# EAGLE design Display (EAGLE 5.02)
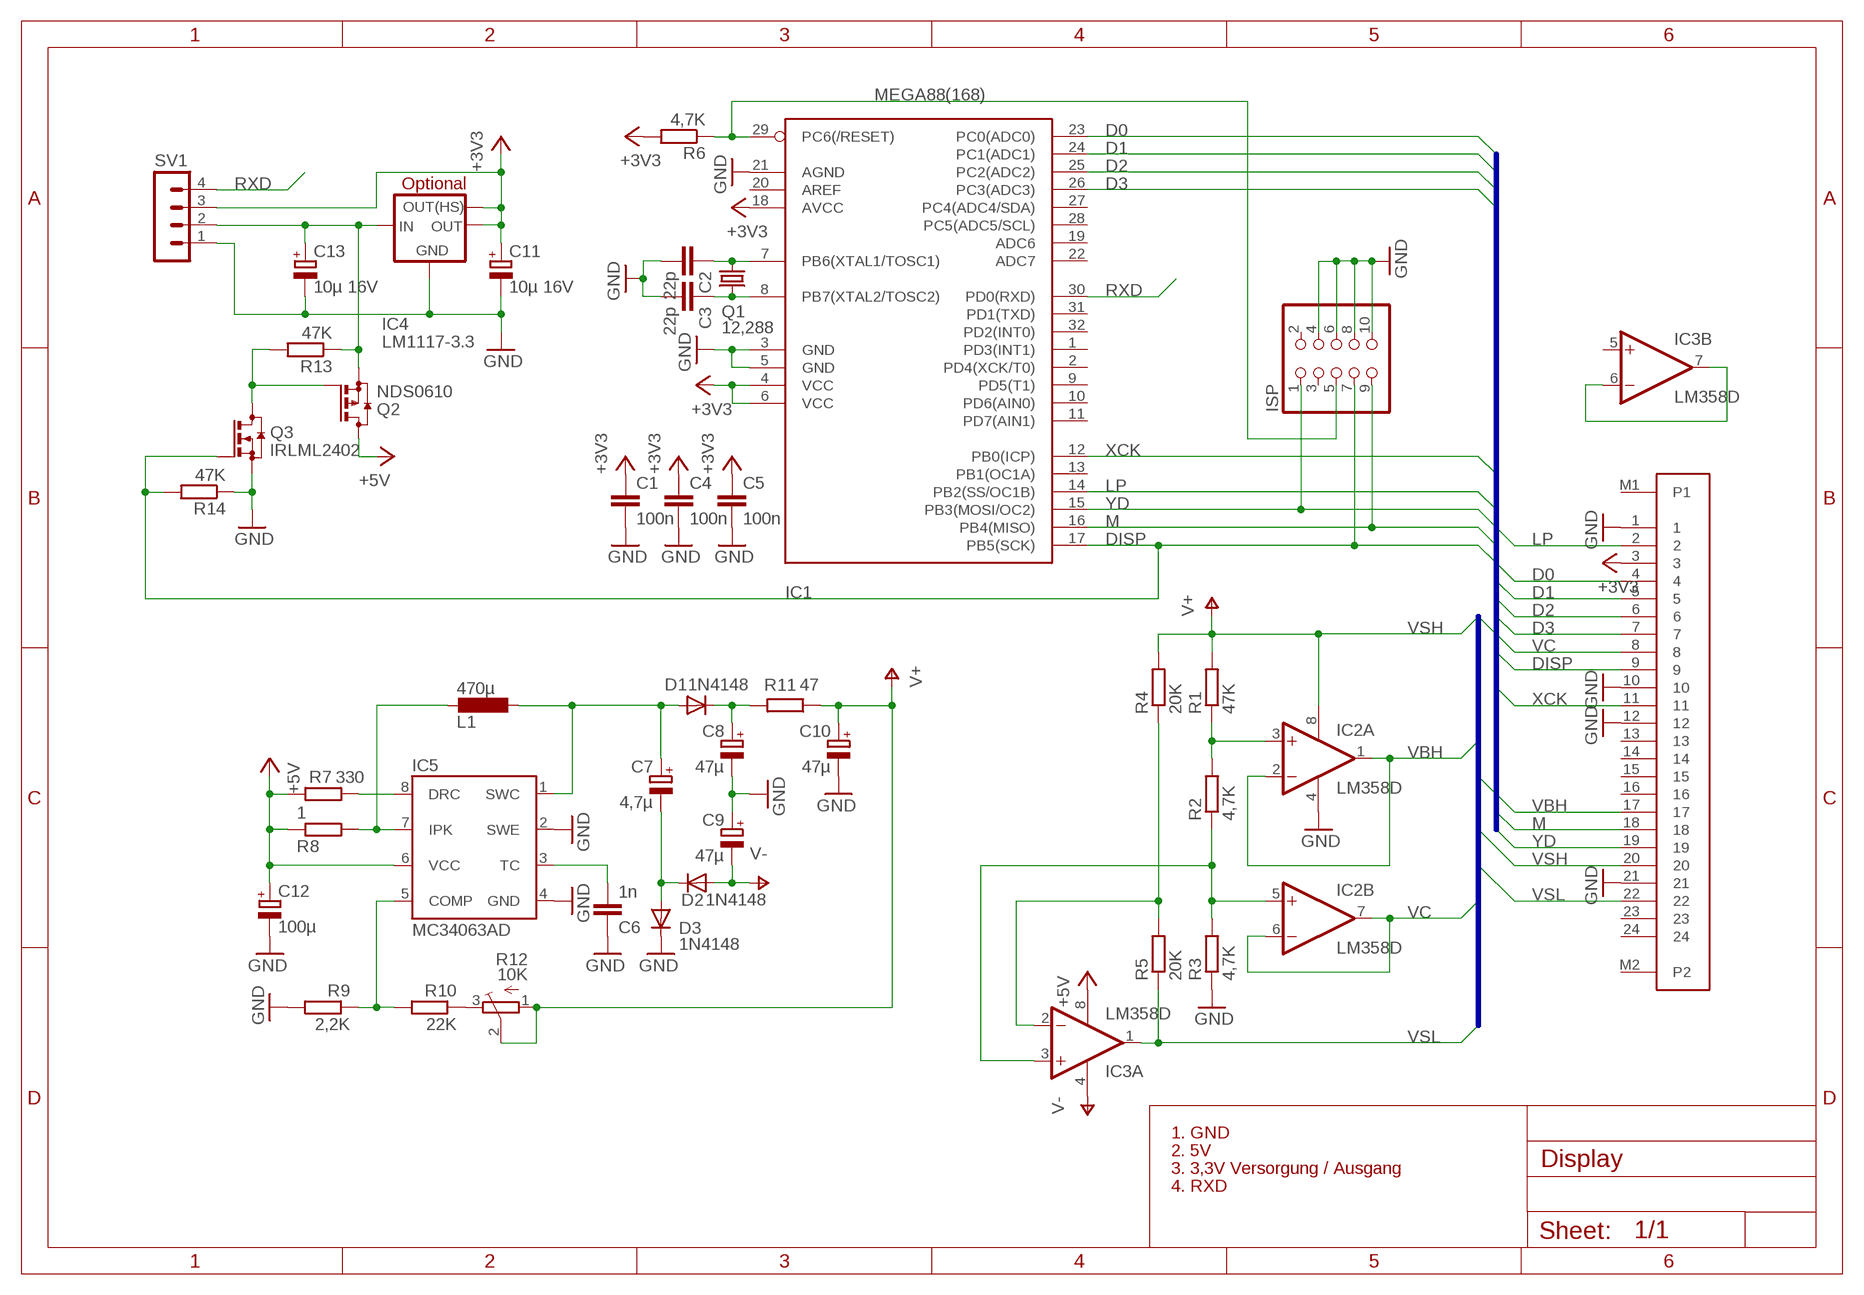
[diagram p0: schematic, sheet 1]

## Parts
C1  100n  C-EUC0402  [C0402]
C2  22p  C-EUC0603  [C0603]
C3  22p  C-EUC0603  [C0603]
C4  100n  C-EUC0402  [C0402]
C5  100n  C-EUC0402  [C0402]
C6  1n  C-EUC0603  [C0603]
C7  4,7µ  CPOL-EU153CLV-0405  [153CLV-0405]
C8  47µ  CPOL-EU153CLV-0605  [153CLV-0605]
C9  47µ  CPOL-EU153CLV-0605  [153CLV-0605]
C10  47µ  CPOL-EU153CLV-0605  [153CLV-0605]
C11  10µ 16V  CPOL-EU153CLV-0405  [153CLV-0405]
C12  100µ  CPOL-EU153CLV-0605  [153CLV-0605]
C13  10µ 16V  CPOL-EU153CLV-0405  [153CLV-0405]
D1  1N4148  DIODE-SOD80C  [SOD80C]
D2  1N4148  DIODE-SOD80C  [SOD80C]
D3  1N4148  DIODE-SOD80C  [SOD80C]
IC1  MEGA88(168)  MEGA8-AI  [TQFP32-08]
IC2  LM358D  [SO08]
IC3  LM358D  [SO08]
IC4  LM1117-3.3  LM1117-HS  [SOT223]
IC5  MC34063AD  [SO08]
ISP  PINHD-2X5_2.54-SMD  [2X05SMD]
L1  470µ  DO3316P  [DO3316P]
Q1  12,288  CRYSTALHC49UP  [HC49UP]
Q2  NDS0610  [SOT23]
Q3  IRLML2402  [SOT23]
R1  47K  R-EU_R0805-MOD  [R0805-MOD]
R2  4,7K  R-EU_R0805-MOD  [R0805-MOD]
R3  4,7K  R-EU_R0805-MOD  [R0805-MOD]
R4  20K  R-EU_R0805-MOD  [R0805-MOD]
R5  20K  R-EU_R0805-MOD  [R0805-MOD]
R6  4,7K  R-EU_R0805-MOD  [R0805-MOD]
R7  330  R-EU_R0805-MOD  [R0805-MOD]
R8  1  R-EU_R0805-MOD  [R0805-MOD]
R9  2,2K  R-EU_R0805-MOD  [R0805-MOD]
R10  22K  R-EU_R0805-MOD  [R0805-MOD]
R11  47  R-EU_R0805-MOD  [R0805-MOD]
R12  10K  TRIM_EU-SM-42/43B  [SM-42/43B]
R13  47K  R-EU_R0805-MOD  [R0805-MOD]
R14  47K  R-EU_R0805-MOD  [R0805-MOD]
SV1  MA04-1  [MA04-1]
X1  FL24-0.5  [FL24-0.5]

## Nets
+3V3: C1.1 C4.1 C5.1 C11.+ IC1.4(VCC) IC1.6(VCC) IC1.18(AVCC) IC4.2(OUT) IC4.4(OUT2) R6.2 SV1.3 X1.3
+5V: C12.+ IC3.8(P:V+) IC5.6(VCC) Q2.3(D) R7.1 R8.1
D0: IC1.23(PC0(ADC0)) X1.4
D1: IC1.24(PC1(ADC1)) X1.5
D2: IC1.25(PC2(ADC2)) X1.6
D3: IC1.26(PC3(ADC3)) X1.7
DISP: IC1.17(PB5(SCK)) ISP.7 Q3.1(G) R14.2 X1.9
GND: C1.2 C2.2 C3.2 C4.2 C5.2 C6.1 C8.- C9.+ C10.- C11.- C12.- C13.- D3.C IC1.3(GND) IC1.5(GND) IC1.21(AGND) IC2.4(P:V-) IC4.1(GND) IC5.2(SWE) IC5.4(GND) ISP.4 ISP.6 ISP.8 ISP.10 Q3.2(S) R3.1 R9.2 R14.1 SV1.1 X1.1 X1.10 X1.12 X1.21
LP: IC1.14(PB2(SS/OC1B)) X1.2
M: IC1.16(PB4(MISO)) ISP.9 X1.18
N$1: C3.1 IC1.8(PB7(XTAL2/TOSC2)) Q1.2
N$2: IC3.6(B:-IN) IC3.7(B:OUT)
N$3: C2.1 IC1.7(PB6(XTAL1/TOSC1)) Q1.1
N$4: IC2.3(A:+IN) R1.1 R2.2
N$5: IC2.5(B:+IN) IC3.3(A:+IN) R2.1 R3.2
N$6: IC1.29(PC6(/RESET)) ISP.5 R6.1
N$7: IC3.2(A:-IN) R4.1 R5.2
N$8: IC5.8(DRC) R7.2
N$9: IC5.7(IPK) L1.1 R8.2
N$10: C7.+ D1.A IC5.1(SWC) L1.2
N$11: C8.+ D1.C R11.2
N$12: IC5.5(COMP) R9.1 R10.2
N$13: C6.2 IC5.3(TC)
N$14: C13.+ IC4.3(IN) Q2.2(S) R13.1 SV1.2
N$15: C7.- D2.C D3.A
N$16: R10.1 R12.3(E)
N$18: Q2.1(G) Q3.3(D) R13.2
RXD: IC1.30(PD0(RXD)) SV1.4
V-: C9.- D2.A IC3.4(P:V-)
VBH: IC2.1(A:OUT) IC2.2(A:-IN) X1.17
VC: IC2.6(B:-IN) IC2.7(B:OUT) X1.8
VSH: C10.+ IC2.8(P:V+) R1.2 R4.2 R11.1 R12.1(A) R12.2(S) X1.20 ; supply symbol labelled V+
VSL: IC3.1(A:OUT) R5.1 X1.22
XCK: IC1.12(PB0(ICP)) X1.11
YD: IC1.15(PB3(MOSI/OC2)) ISP.1 X1.19
Unconnected: IC1.1(PD3(INT1)) IC1.2(PD4(XCK/T0)) IC1.9(PD5(T1)) IC1.10(PD6(AIN0)) IC1.11(PD7(AIN1)) IC1.13(PB1(OC1A)) IC1.19(ADC6) IC1.20(AREF) IC1.22(ADC7) IC1.27(PC4(ADC4/SDA)) IC1.28(PC5(ADC5/SCL)) IC1.31(PD1(TXD)) IC1.32(PD2(INT0)) IC3.5(B:+IN) ISP.2 ISP.3 X1.13 X1.14 X1.15 X1.16 X1.23 X1.24 X1.M1(P1) X1.M2(P2)

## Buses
D[0..3],LP,XCK,M,YD,DISP
VSH,VBH,VC,VSL

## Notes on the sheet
- Optional
- 1. GND
- 2. 5V
- 3. 3,3V Versorgung / Ausgang
- 4. RXD

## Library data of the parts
C1-C6 = rcl:C-EU: CAPACITOR, European symbol
C7-C13 = rcl:CPOL-EU: POLARIZED CAPACITOR, European symbol
D1-D3 = diode:DIODE-: DIODE
IC1 = atmel:MEGA8: MICROCONTROLLER 8 Kbytes FLASH, 1 kbytes SRAM, 512 bytes EEPROM, USART, 6-channel 10 bit ADC, 2-channel 8 bit ADC Pin compatible with Atmega48, ATMega88, ATMega168 Source: avr.lbr
IC2 IC3 = linear:LM358: OP AMP also LM158; LM258; LM2904 Source: http://cache.national.com/ds/LM/LM158.pdf
IC4 = v-reg-3:LM1117-HS
IC5 = v-reg-3:MC34063A: 1.5A Step-Up/Down/Inverting Switching Regulator NPN Darlington Switch, Vin 3V to 40V, Current Limiter Input, adjustable Frequency up to 100kHz
ISP = pinhead-1:PINHD-2X5: PIN HEADER
L1 = inductor-coilcraft:DO3316P: COILCRAFT
Q1 = crystal:CRYSTAL: CRYSTAL
Q2 = SMD MOSFET:NDS0610: P-CHANNEL MOS FET
Q3 = SMD MOSFET:IRLML2402: N-CHANNEL MOS FET
R1-R11 R13 R14 = rcl:R-EU_: RESISTOR, European symbol
R12 = pot:TRIM_EU-: POTENTIOMETER
SV1 = con-lstb:MA04-1: PIN HEADER
X1 = Flexprint:FL24-0.5

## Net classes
0 digital: width 0.203 mm, clearance 0.102 mm

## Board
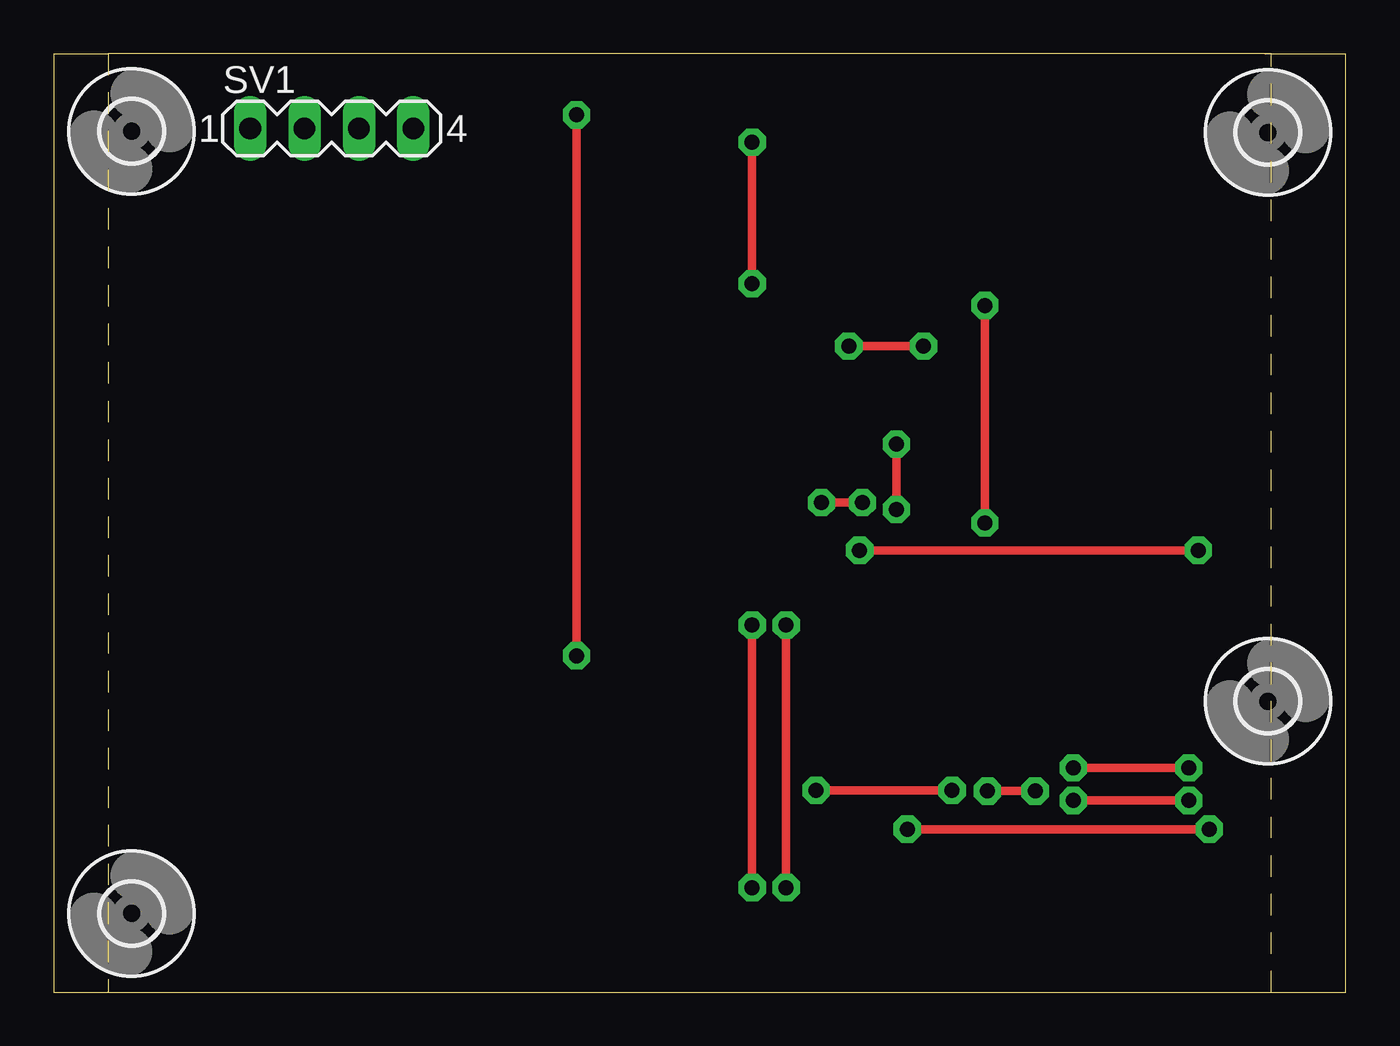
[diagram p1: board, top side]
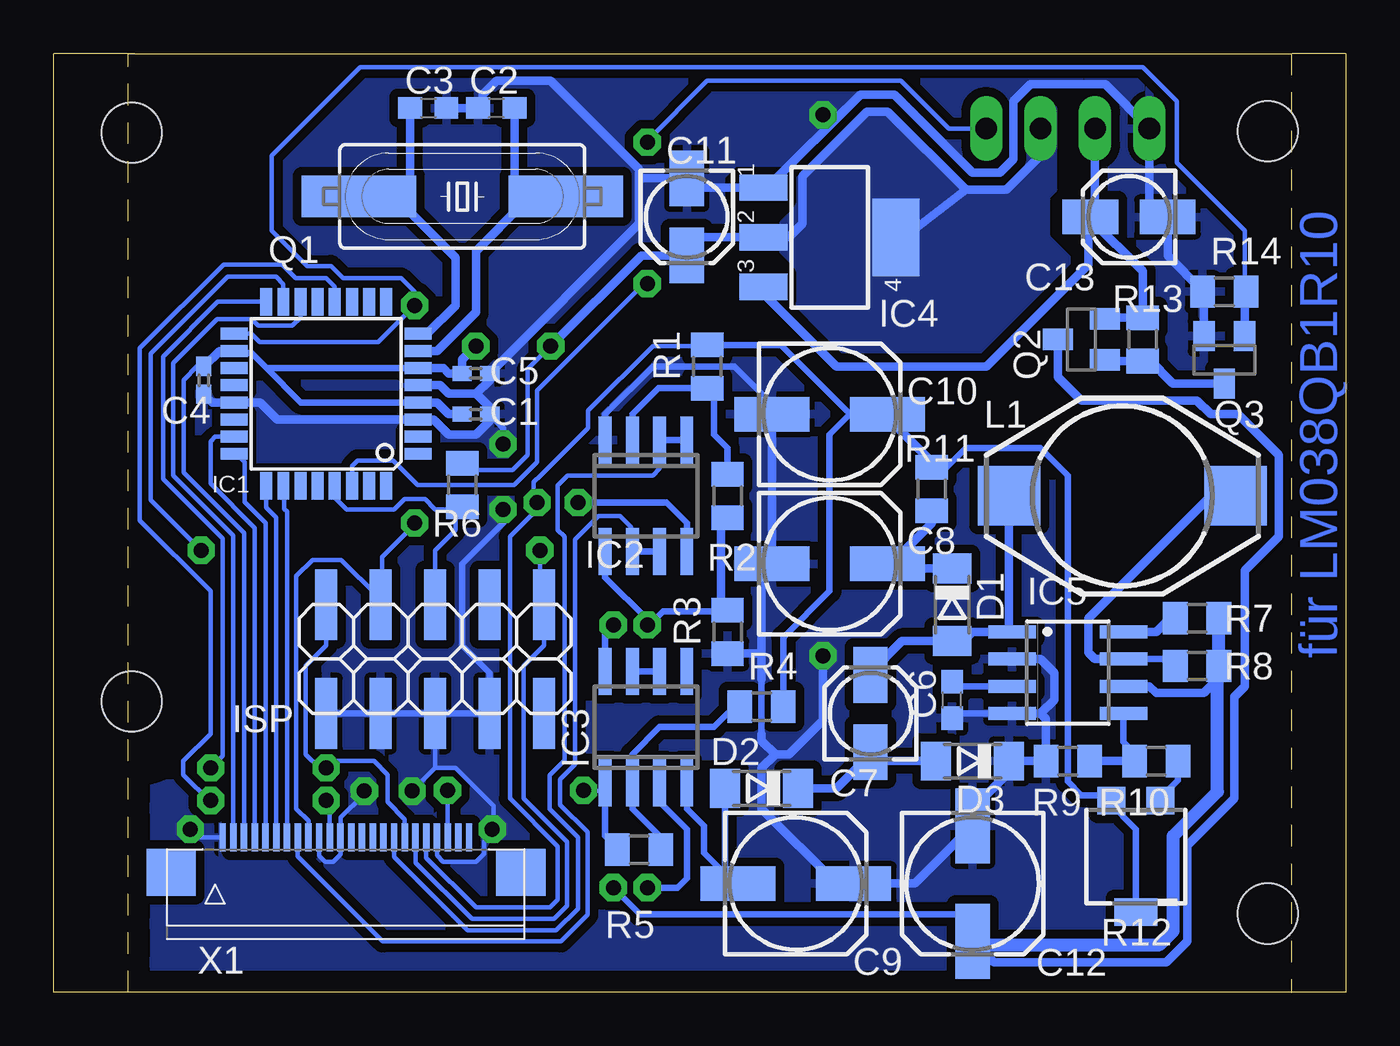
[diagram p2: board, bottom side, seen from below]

Size 60.31 x 43.81 mm. Coordinates in mm from the lower left corner, seen from the top.
Outline: 2.53,0 2.54,0 2.54,43.81 56.82,43.81 56.82,0
Outline: 2.53,0 56.82,0
Outline: 60.31,43.81 60.31,0 56.82,0
Outline: 56.51,0 56.82,0
Outline: 56.51,43.82 60.31,43.82
Outline: 0,43.81 0,0 2.53,0
Outline: 0,43.82 2.53,43.82
Copper layers (1*16): Top 0.035mm / dielectric 1.5mm / Bottom 0.035mm
Design rules "default": minimum track width 10mil, minimum drill 24mil, track to track 8mil, track to pad 8mil, pad to pad 8mil, via to via 8mil, smd to smd 8mil, copper to edge 40mil, drill to drill 8mil, minimum pad ring 10mil, minimum via ring 8mil, stop-mask expansion 4mil, vias tented up to drill 0mil, thermal gap 10mil

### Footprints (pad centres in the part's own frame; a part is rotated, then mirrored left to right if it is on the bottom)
C0402 = smd 0.9 x 0.7: 1 -0.65,0; 2 0.65,0
C0603 = smd 1.1 x 1: 1 -0.85,0; 2 0.85,0
153CLV-0405 = smd 2.6 x 1.6: + 1.8,0; - -1.8,0
153CLV-0605 = smd 3.5 x 1.6: + 2.7,0; - -2.7,0
SOD80C = smd 1.4 x 1.8: A 1.7,0; C -1.7,0
TQFP32-08 = smd 1.27 x 0.559: 1 -4.293,2.8; 2 -4.293,2; 3 -4.293,1.2; 4 -4.293,0.4; 5 -4.293,-0.4; 6 -4.293,-1.2; 7 -4.293,-2; 8 -4.293,-2.8; 17 4.293,-2.8; 18 4.293,-2; 19 4.293,-1.2; 20 4.293,-0.4; 21 4.293,0.4; 22 4.293,1.2; 23 4.293,2; 24 4.293,2.8 | smd 0.559 x 1.27: 9 -2.8,-4.293; 10 -2,-4.293; 11 -1.2,-4.293; 12 -0.4,-4.293; 13 0.4,-4.293; 14 1.2,-4.293; 15 2,-4.293; 16 2.8,-4.293; 25 2.8,4.293; 26 2,4.293; 27 1.2,4.293; 28 0.4,4.293; 29 -0.4,4.293; 30 -1.2,4.293; 31 -2,4.293; 32 -2.8,4.293
SO08 = smd 0.6 x 2.2: 1 -1.905,-2.6; 2 -0.635,-2.6; 3 0.635,-2.6; 4 1.905,-2.6; 5 1.905,2.6; 6 0.635,2.6; 7 -0.635,2.6; 8 -1.905,2.6
SOT223 = smd 1.219 x 2.235: 1 -2.311,-3.099; 2 0,-3.099; 3 2.311,-3.099 | smd 3.6 x 2.2: 4 0,3.099
2X05SMD = smd 1.016 x 3.302: 1 -1.27,-3.81; 2 -1.27,1.27; 3 1.27,-3.81; 4 1.27,1.27; 5 3.81,-3.81; 6 3.81,1.27; 7 6.35,-3.81; 8 6.35,1.27; 9 8.89,-3.81; 10 8.89,1.27
DO3316P = smd 2.92 x 2.79: 1 -5.28,0; 2 5.28,0
HC49UP = smd 5.334 x 1.93: 1 -4.826,0; 2 4.826,0
SOT23 = smd 1 x 1.4: 1 -0.95,-1.1; 2 0.95,-1.1; 3 0,1.1
R0805-MOD = smd 1.146 x 1.5: 1 -1.014,0; 2 1.014,0
SM-42/43B = smd 1.3 x 1.3: 1 2.6,1.15; 3 2.6,-1.15 | smd 1.3 x 2: 2 -2.6,0
MA04-1 = drill 1.016 long: 1 -3.81,0; 2 -1.27,0; 3 1.27,0; 4 3.81,0
2,8 = hole 2.8: 0,0
FL24-0.5 = smd 0.3 x 1.3: 1 0,-0.04; 2 0.5,-0.04; 3 1,-0.04; 4 1.5,-0.04; 5 2,-0.04; 6 2.5,-0.04; 7 3,-0.04; 8 3.5,-0.04; 9 4,-0.04; 10 4.5,-0.04; 11 5,-0.04; 12 5.5,-0.04; 13 6,-0.04; 14 6.5,-0.04; 15 7,-0.04; 16 7.5,-0.04; 17 8,-0.04; 18 8.5,-0.04; 19 9,-0.04; 20 9.5,-0.04; 21 10,-0.04; 22 10.5,-0.04; 23 11,-0.04; 24 11.5,-0.04 | smd 2.3 x 2.2: M1 13.911,-1.68; M2 -2.4,-1.68

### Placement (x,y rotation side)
C1  40.6,26.98 0 bottom
C2  39.65,41.27 180 bottom
C3  42.82,41.27 0 bottom
C4  53.3,28.57 270 bottom
C5  40.6,28.89 0 bottom
C6  18.38,13.65 90 bottom
C7  22.19,13.01 90 bottom
C8  24.09,20 0 bottom
C9  25.68,5.07 0 bottom
C10  24.09,26.98 0 bottom
C11  30.76,36.19 270 bottom
C12  17.42,5.07 270 bottom
C13  10.12,36.19 180 bottom
D1  18.38,18.09 270 bottom
D2  27.27,9.52 180 bottom
D3  17.42,10.79 180 bottom
IC1  47.59,27.93 180 bottom
IC2  32.66,23.17 180 bottom
IC3  32.66,12.38 0 bottom
IC4  24.09,35.24 270 bottom
IC5  12.98,14.92 270 bottom
ISP  38.7,14.28 180 bottom
L1  10.44,23.17 180 bottom
Q1  41.24,37.14 180 bottom
Q2  12.34,30.48 90 bottom
Q3  5.68,29.52 180 bottom
R1  29.81,29.21 90 bottom
R2  28.85,23.17 90 bottom
R3  28.85,16.82 90 bottom
R4  27.27,13.33 0 bottom
R5  32.98,6.66 0 bottom
R6  41.24,23.68 90 bottom
R7  6.95,17.46 180 bottom
R8  6.95,15.23 180 bottom
R9  12.98,10.79 180 bottom
R10  8.85,10.79 180 bottom
R11  19.33,23.49 270 bottom
R12  9.8,6.35 90 bottom
R13  9.49,30.48 270 bottom
R14  5.68,32.7 0 bottom
SV1  12.98,40.32 0 top
U$1  [2,8]  56.67,13.58 0 top
U$2  [2,8]  56.67,40.13 0 top
U$3  [2,8]  3.65,40.19 0 top
U$4  [2,8]  3.65,3.68 0 top
X1  52.42,7.27 0 bottom

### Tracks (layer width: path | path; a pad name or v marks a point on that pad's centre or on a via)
+3V3  (via drill 0.7 pad 1.27)
  Top 0.406: v37.11,30.16 v40.6,30.16
  Bottom 0.203: X1.3 51.42,7.38 51.46,7.42 51.42,7.47 51.42,21.45 54.24,24.27 54.24,28.59 53.6,29.22 C4.1 | R6.2 40.98,24.57 40.79,24.38 38.89,24.38 38.19,25.08 38.19,29.08 v37.11,30.16 | v37.11,30.16 37.24,30.03 | v37.11,30.16
  Bottom 0.305: IC1.6 50.37,29.14 | IC1.4 48.77,27.53 50.37,29.14 | 50.37,29.14 51.08,29.84 51.71,29.84 51.81,29.93 IC1.18
  Bottom 0.406: IC1.6 42.12,29.14 41.87,28.89 C5.1 41.24,28.89 41.24,29.52 v40.6,30.16 | IC1.4 42.42,27.53 41.87,26.98 C1.1 | C4.1 53.3,29.21 52.57,29.93 IC1.18 | 17.74,37.46 21.39,41.11 22.35,41.11 25.36,38.1 25.36,35.87 26,35.24 IC4.2 30.12,35.24 30.76,34.6 C11.+ 32.88,34.39 v37.11,30.16 | 17.74,37.46 15.84,37.46 14.25,39.05 SV1.3 | IC4.4 20.6,35.24 17.74,37.46
  pour Bottom (isolate 0.406, no thermals): 13.61,41.27 13.61,37.46 13.93,37.14 13.93,35.24 12.98,34.28 12.98,33.97 17.11,29.84 23.46,29.84 25.68,32.06 25.68,33.97 26.31,34.6 26.31,35.87 25.68,36.51 25.68,38.09 22.31,41.46 21.27,41.46 17.58,37.78 15.52,37.78 14.88,38.41 14.88,41.27
+5V  (via drill 0.7 pad 1.27)
  Top 0.406: v34.19,4.88 v34.19,17.14
  Bottom 0.305: IC3.8 34.57,16.76 v34.19,17.14 | v34.19,4.88 32.95,3.65 18.54,3.65 17.9,3.65 17.42,3.17 C12.+
  Bottom 0.406: IC5.6 9.17,14.28 8.85,13.96 6.63,13.96 5.99,14.6 5.99,14.92 | R7.1 5.99,17.46 5.93,17.4 | Q2.3 13.44,28.72 12.34,27.62 6.95,27.62 6.31,26.98 5.04,26.98 3.14,25.08 3.14,21.27 4.72,19.68 4.72,14.28 5.17,13.84 5.2,13.81 5.2,9.04 7.39,6.85 7.39,2.38 8.38,1.39 16.44,1.39 C12.+
  Bottom 0.61: 5.93,17.4 R8.1 5.93,14.98 5.99,14.92 5.99,9.36 8.06,7.3 8.06,2.85 8.69,2.22 17.42,2.22 C12.+
D0
  Bottom 0.203: IC1.23 52.76,25.93 52.98,25.71 52.98,23.74 50.92,21.68 50.92,7.45 50.89,7.42 50.92,7.39 X1.4
D1
  Bottom 0.203: IC1.24 51.77,25.14 51.4,24.76 51.4,22.89 50.42,21.91 X1.5
D2
  Bottom 0.203: 50.55,23.38 50.39,23.55 IC1.25 50.39,22.64 49.92,22.17 49.92,7.44 49.94,7.42 49.92,7.41 X1.6
D3
  Bottom 0.203: 49.42,23.42 49.59,23.59 IC1.26 49.59,23.33 49.56,23.3 49.56,22.57 49.42,22.43 X1.7
DISP  (via drill 0.7 pad 1.27)
  Top 0.406: v43.46,32.06 v43.46,21.9
  Bottom 0.203: 45.17,18.47 46.89,20.19 48.22,20.19 48.98,19.43 48.98,8.57 48.42,8 X1.9 | X1.9 | X1.9 | IC1.17 51.09,30.73 50.7,30.35 45.17,30.35 v43.46,32.06 43.46,32.7 44.09,33.33 46.79,33.33 47.36,33.9 48.48,33.9 50.13,35.56 50.13,39.05 46,43.18 9.49,43.18 7.9,41.59 7.9,38.73 4.72,35.56 4.72,32.7 R14.2 4.66,32.44 4.73,32.38 | v43.46,21.9 43.46,21.84 44.98,20.32 44.98,18.66 45.17,18.47 | 45.17,18.47 45.05,18.35 ISP.7
  Bottom 0.406: Q3.1 4.73,32.38
GND  (via drill 0.7 pad 1.27)
  Top 0.406: v39.33,25.59 v39.33,22.54 | v43.59,9.39 v45.81,9.39 | v39.84,7.61 v53.94,7.61 | v24.41,15.71 v24.41,40.95
  Bottom 0.203: X1.12 46.92,6.44 47.27,6.09 47.65,6.09 47.92,6.36 X1.10 | X1.21 42.42,6.39 42.13,6.09 40.6,6.09 40.22,6.47 40.22,7.04 39.65,7.61 | 46.89,7.23 | X1.12 46.89,7.23 | 46.89,7.23 46.95,7.3 | ISP.6 42.51,10.47 | 42.51,10.47 v43.59,9.39 | v45.81,9.39 45.87,9.33 45.87,9.2 46.92,8.16 X1.12 | 39.65,7.61 39.78,7.81 39.78,8.69 41.55,10.47 42.51,10.47 | X1.1 53.56,7.23 v53.94,7.61 | 39.65,7.61 v39.84,7.61 | 6.63,32.7 | 27.02,37.55 IC4.1
  Bottom 0.305: C6.1 18.16,12.8 18.06,13.01 IC5.4 | 27.27,12.06 27.27,14.6 | ISP.10 ISP.8 ISP.6 ISP.4 39.97,14.92 41.24,16.19 41.24,20 39.33,21.9 v39.33,22.54 | v39.33,25.59 39.33,26.35 39.97,26.98 | 26.95,26.98 26.95,27.62 28.54,29.21 32.35,29.21 34.57,26.98 IC2.4 | C12.-
  Bottom 0.406: IC5.2 14.25,15.55 13.61,14.92 13.61,13.65 14.25,13.01 | 14.25,13.01 IC5.4 | 14.25,13.01 13.99,12.76 R9.2 D3.C 15.72,10.27 17.42,8.57 C12.- | 27.27,14.6 27.27,15.87 | 27.27,15.87 27.27,19.36 26.63,20 C8.- 26.79,26.82 26.95,26.98 C10.- | 40.6,41.27 C3.2 | IC1.5 42.27,28.34 41.87,27.93 40.6,27.93 | 40.6,27.93 39.95,28.59 C5.2 39.95,28.9 32.98,35.87 32.98,38.1 | C1.2 39.95,27.28 40.6,27.93 | C1.2 39.97,26.98 | C4.2 53.3,27.93 52.9,27.53 IC1.21 50.68,27.53 49.88,26.73 IC1.3 42.58,26.73 41.87,26.03 40.6,26.03 39.95,26.68 C1.2 | 32.98,38.1 32.98,38.41 37.11,42.54 39.65,42.54 40.28,41.9 40.28,41.59 40.6,41.27 | 40.6,41.27 C2.2 | Q3.2 6.63,32.7 6.82,32.7 | 6.82,32.7 6.88,32.76 | 6.82,32.7 R14.1 6.69,32.76 8.32,34.39 C13.- 8.53,36.19 9.17,36.82 SV1.1 11.23,42.38 14.73,42.38 15.52,41.59 15.52,38.89 16.15,38.25 17.42,38.25 21.08,41.91 22.66,41.9 | 22.66,41.9 27.02,37.55 | R3.1 27.27,15.81 27.27,15.87 | IC4.1 30.53,37.55 30.76,37.78 C11.- 32.88,37.99 32.98,38.1 | 26.63,11.11 27.27,10.47 27.27,8.57 23.77,5.07 C9.+ 20.12,5.07 C12.- | 26.63,11.11 26,11.11 24.41,12.69 v24.41,15.71 | 27.27,12.06 27.27,11.74 26.63,11.11 | v24.41,40.95 24.41,41.11 23.93,40.64 22.66,41.9
  pour Bottom (isolate 0.406): 2.82,43.49 2.82,0.31 56.48,0.31 56.48,43.49 38.06,43.49 12.34,43.49 12.34,42.54 14.57,42.54 15.52,41.59 15.52,39.05 16.15,38.41 17.42,38.41 21.23,42.22 22.5,42.22 26,38.73 28.54,38.73 29.17,38.09 29.17,34.6 23.77,29.21 16.79,29.21 12.03,33.97 12.03,43.49
LP
  Bottom 0.203: IC1.14 48.79,31.5 49.17,31.11 50.76,31.11 51.08,31.43 52.67,31.43 54.73,29.36 54.73,24.13 51.92,21.31 X1.2
M  (via drill 0.7 pad 1.27)
  Top 0.406: v47.59,10.47 v52.98,10.47
  Bottom 0.203: IC1.16 52.66,32.23 55.21,29.68 55.21,23.97 52.41,21.17 52.41,11.04 v52.98,10.47 | ISP.9 47.59,16.19 48.54,15.23 48.54,11.11 47.9,10.47 v47.59,10.47 47.27,10.79 45.36,10.79 44.73,10.16 44.73,8.88 43.92,8.08 X1.18
N$1
  Bottom 0.406: Q1.2 45.68,37.14 45.36,36.82 44.09,36.82 | C3.1 43.67,37.25 44.09,36.82 | IC1.8 42.88,30.73 41.55,32.06 41.55,34.28 44.09,36.82
N$2
  Bottom 0.305: IC3.7 33.3,14.92 33.24,14.98 IC3.6
N$3
  Bottom 0.406: Q1.1 36.79,37.14 37.11,36.82 38.38,36.82 | 38.38,36.82 38.38,37.14 38.8,37.56 C2.1 | IC1.7 42.41,29.93 40.6,31.75 40.6,34.6 38.38,36.82
N$4
  Bottom 0.305: 33.3,25.71 IC2.3 33.3,26.98 32.09,28.19 R1.1 29.81,28.25 29.49,27.93 29.49,26.03 28.85,25.39 R2.2
N$5  (via drill 0.7 pad 1.27)
  Top 0.406: v32.6,4.88 v32.6,17.14
  Bottom 0.305: IC2.5 34.57,19.36 32.6,17.39 v32.6,17.14 32.51,17.14 31.87,17.78 29.17,17.78 | IC3.3 32.03,8.88 30.76,7.61 30.76,5.33 31.2,4.88 v32.6,4.88
  Bottom 0.406: 29.17,17.78 29.17,17.84 | 29.17,17.84 R3.2 | R2.1 29.17,22.16 29.17,17.84
N$6
  Bottom 0.203: 42.25,17.4 ISP.5 42.51,20.63 41.55,21.59 41.55,22.54 | IC1.29 47.19,23.09 46.63,22.54 44.41,22.54 43.94,23.01 42.98,23.01 42.51,22.54 41.55,22.54 | 41.55,22.54 41.36,22.73 41.3,22.67 R6.1 41.43,22.67 41.55,22.54
N$7
  Bottom 0.305: R5.2 31.97,7.24 33.3,8.57 IC3.2 33.3,11.11 32.03,12.38 29.49,12.38 28.85,13.01 28.22,13.01 28.28,13.07 R4.1
N$8
  Bottom 0.406: R7.2 8.22,17.46 8.85,16.82 IC5.8
N$9
  Bottom 0.305: R8.2 8.22,15.23 8.53,15.55 IC5.7
  Bottom 0.406: L1.1 6.31,23.17 12.03,17.46 12.03,15.87 11.71,15.55 IC5.7
N$10
  Bottom 0.406: L1.2 15.72,17.02 15.52,16.82 IC5.1 17.42,16.82 17.85,16.39 D1.A 20.71,16.39 22.19,14.92 C7.+
N$11
  Bottom 0.406: 21.55,20 C8.+ 21.23,20 | R11.2 19.33,21.9 21.23,20 | D1.C 21.03,19.79 21.23,20
N$12
  Bottom 0.305: IC5.5 10.38,11.68 9.8,11.11
  Bottom 0.406: 9.8,11.11 9.87,11.05 R10.2 R9.1
N$13
  Bottom 0.305: C6.2 18.38,14.28 IC5.3
N$14
  Bottom 0.203: Q2.2 11.08,31.43 11.01,31.49 | 11.71,36.51 12.03,36.19 C13.+ 11.92,36.08
  Bottom 0.406: 11.01,31.49 R13.1 9.49,33.65 11.92,36.08 | 11.71,36.51 SV1.2 | 12.03,36.19 12.03,33.97 16.79,29.21 23.77,29.21 27.27,32.7 27.19,32.77 27.08,32.77 27.08,32.93 | 27.08,32.93 27.08,32.95 | 27.08,32.93 IC4.3
N$15
  Bottom 0.406: 22.29,11.21 22.5,11.43 | 22.29,11.21 C7.- 22.19,11.11 | D3.A 21.87,10.79 22.19,11.11 | 22.19,11.11 22.29,11.21 | D2.C 23.77,9.52 22.19,11.11
N$16
  Bottom 0.305: R12.3 8.65,9.08 7.84,9.9 R10.1
N$18
  Bottom 0.203: 9.17,29.52 R13.2 | Q2.1 11.08,29.53 11.01,29.46
  Bottom 0.406: Q3.3 8.07,28.42 9.17,29.52 | R13.2 11.01,29.46
RXD  (via drill 0.7 pad 1.27)
  Top 0.406: v32.6,39.68 v32.6,33.08
  Bottom 0.203: IC1.30 46.39,24.56 46.13,24.82 44.48,24.82 43.33,23.68 38.82,23.68 37.74,24.76 37.74,28.09 32.76,33.08 v32.6,33.08 | SV1.4 18.54,40.32 20.76,42.54 29.81,42.54 32.66,39.68 v32.6,39.68
V-
  Bottom 0.305: D2.A 28.97,5.51 28.54,5.07 | IC3.4 30.76,8.57 29.97,7.77 29.97,6.5 28.54,5.07 | C9.- 28.54,5.07
VBH
  Bottom 0.203: X1.17 44.42,6.32 40.98,2.88 36.86,2.88 35.84,3.9 35.84,7.23 37.17,8.57 37.17,10.12 36.47,10.82 36.47,21.27 36.79,21.59 36.79,23.65 36.32,24.12 32.35,24.12 32.03,24.44 IC2.2
  Bottom 0.305: IC2.2 32.03,25.71 31.97,25.77 IC2.1
VC
  Bottom 0.203: 33.18,20.57 33.17,20.57 | 33.18,20.57 IC2.6 | 33.18,20.57 33.36,20.76 33.36,21.71 33.87,22.22 34.89,22.22 35.97,21.14 35.97,10.63 36.66,9.93 36.66,8.76 35.4,7.49 35.4,3.61 36.63,2.38 44.95,2.38 48.92,6.34 X1.8
  Bottom 0.305: IC2.6 33.3,20.63 33.24,20.57 IC2.7
VSH  (via drill 0.7 pad 1.27)
  Top 0.406: v37.74,22.85 v35.84,22.85
  Bottom 0.203: X1.20 42.92,6.28 40.6,3.96 37.14,3.96 36.79,4.31 36.79,6.82 39.01,9.04 39.01,21.27 37.9,22.38 37.9,22.85 | 37.9,22.85 37.9,23.81 37.59,24.12 35.36,26.35 35.36,27.14 32.35,30.16 29.81,30.16 R1.2 | 37.9,22.85 v37.74,22.85
  Bottom 0.305: R12.2 9.8,7.61 11.07,8.88 11.07,9.2 12.34,9.2 12.98,9.84 12.98,24.12 14.25,25.39 17.74,25.39 18.63,24.5 R11.1 | 30.76,20.63 IC2.8 30.76,21.9 31.71,22.85 v35.84,22.85 | 21.55,26.98 23.14,26.98 | R4.2 26.25,16.57 24.09,18.73 24.09,26.03 23.14,26.98 | R1.2 26.38,30.22 23.14,26.98
  Bottom 0.406: 11.07,8.88 11.01,8.94 R12.1 | C10.+ 21.55,26.98 19.33,24.76 R11.1
VSL  (via drill 0.7 pad 1.27)
  Top 0.406: v35.59,9.42 v41.94,9.42
  Bottom 0.203: IC3.1 34.57,9.84 | 34.57,9.52 34.7,9.39 36.03,9.39 v35.59,9.42 | 41.94,7.23 | 41.94,7.23 X1.22 | 41.94,7.23 41.92,7.25 | v41.94,9.42 41.94,7.23
  Bottom 0.305: R5.1 34.57,7.3 34.57,9.52 IC3.1
XCK  (via drill 0.7 pad 1.27)
  Top 0.406: v47.59,8.95 v52.98,8.95
  Bottom 0.203: IC1.12 47.19,32.93 47.59,33.33 49.02,33.33 49.65,33.97 52.38,33.97 56.29,30.06 56.29,22.03 52.98,18.73 52.98,12.06 54.25,10.79 54.25,10.16 52.98,8.88 v52.98,8.95 | 47.42,8.78 47.42,8.59 | X1.11 47.42,8.78 | 47.42,8.78 v47.59,8.95
YD  (via drill 0.7 pad 1.27)
  Top 0.406: v37.62,20.63 v53.43,20.63
  Bottom 0.203: X1.19 43.42,6.05 40.79,3.42 36.95,3.42 36.35,4.03 36.35,7.01 38.38,9.04 38.38,15.23 37.43,16.19 ISP.1 37.43,18.22 37.36,18.28 37.62,18.54 v37.62,20.63 | IC1.15 49.59,33.05 49.94,33.4 52.19,33.4 55.78,29.81 55.78,22.98 v53.43,20.63

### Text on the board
Bottom: für LM038QB1R10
